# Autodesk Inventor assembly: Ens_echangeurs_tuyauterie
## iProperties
Shininess: 64.0
Length Units: 11269
Angle Units: 11279
Time Units: 11290
Mass Units: 11283
Length Display Precision: 3
Angle Display Precision: 2
Compacted: True
Created: 2008-03
Part Number: Ens_echangeurs_tuyauterie
Document SubType Name: Assembly
Designer: Pascal
Density: 0.0
Volumn: 0.0
Area: 0.0
PropertySet Name: Model Information
Control State: 0
Master: False
Checked Out: False
Author: Pascal
